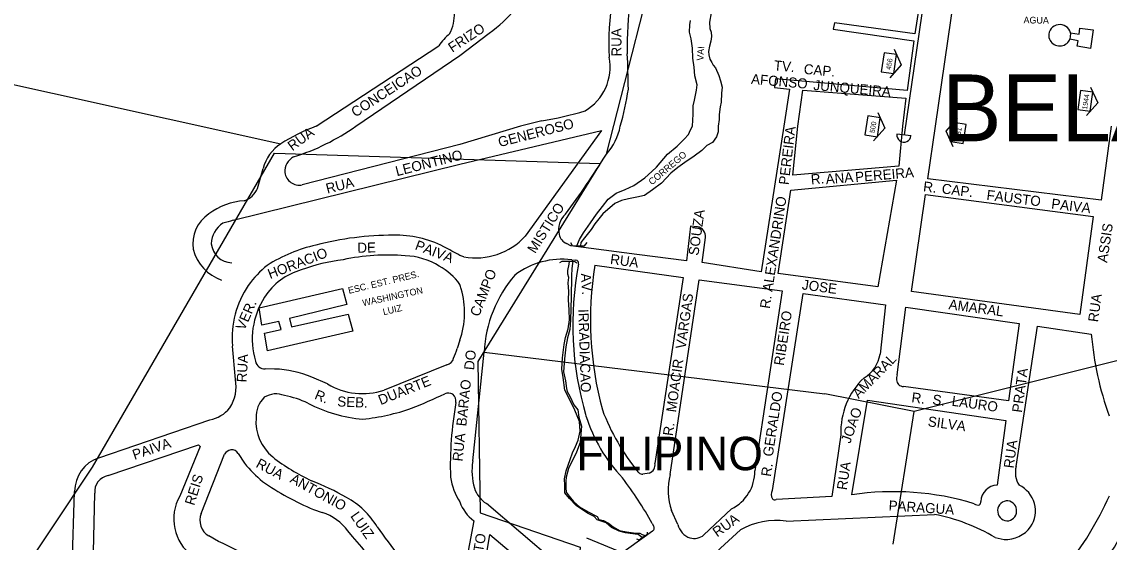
# Model space of a CAD drawing. Extents: x 325709 to 364434, y 7573432 to 7597073.
# Drawn here: x 337419 to 338070, y 7588753 to 7589064 of the extents above; entities that cross this region are included whole.
import ezdxf

# ---------------------------------------------------------------- set-up
doc = ezdxf.new("R2010")
doc.units = 0
for name, color, linetype in [('EDIFEXISTENT', 7, 'Continuous'), ('EDIFIDENTIF', 7, 'Continuous'), ('EDIFOBRAEXIS', 7, 'Continuous'), ('FORMATO', 7, 'Continuous'), ('LIMITE_BAIRROS_MUNICIPIOS', 7, 'Continuous'), ('LOGRADOURO', 7, 'Continuous'), ('LOGRADOURO_TEXTO', 7, 'Continuous'), ('NUM_REF', 7, 'Continuous'), ('TUBO_PEAD_GN_63', 7, 'Continuous')]:
    doc.layers.add(name, color=color, linetype=linetype)

# ---------------------------------------------------------------- blocks, each defined once
blk = doc.blocks.new('NUM_REF')
at = {"layer": 'NUM_REF'}
blk.add_lwpolyline([(-4.3125, 0.9375), (0, 3.75), (4.3125, 0.9375)], dxfattribs=at)
blk.add_lwpolyline([(2.875, -1.875), (2.875, 1.875), (-2.875, 1.875), (-2.875, -1.875)], close=True, dxfattribs=at)

msp = doc.modelspace()

# ---------------------------------------------------------------- linework, layer by layer
at = {"layer": 'EDIFEXISTENT'}
for p, q in [((338051.81, 7589056.99), (338052.19, 7589060.59)), ((338052.19, 7589060.59), (338060.07, 7589059.58)), ((338060.07, 7589059.58), (338058.51, 7589048.44)), ((338051.09, 7589053.04), (338046.15, 7589054.05)), ((338046.59, 7589057.82), (338051.81, 7589056.99)), ((338050.63, 7589049.78), (338051.09, 7589053.04)), ((338058.51, 7589048.44), (338050.63, 7589049.78)), ((337747.63, 7588932.35), (337748.55, 7588930.51)), ((337748.55, 7588930.51), (337751.34, 7588930.39)), ((337751.34, 7588930.39), (337753.58, 7588930.33)), ((337753.58, 7588930.33), (337756.01, 7588930.31)), ((337756.01, 7588930.31), (337757.52, 7588932.3)), ((337741.25, 7588920.34), (337742.68, 7588921.14)), ((337742.68, 7588921.14), (337746.99, 7588921.11)), ((337746.99, 7588921.11), (337748.95, 7588921.1)), ((337748.95, 7588921.1), (337750.16, 7588921.04)), ((337750.16, 7588921.04), (337751.4, 7588920.24)), ((337561.34, 7588893.15), (337611.22, 7588904.7)), ((337611.22, 7588904.7), (337613.85, 7588895.12)), ((337563.07, 7588882.93), (337561.34, 7588893.15)), ((337613.85, 7588895.12), (337579.56, 7588886.81)), ((337580.81, 7588881.87), (337614.63, 7588889.5)), ((337614.63, 7588889.5), (337617.41, 7588879.27)), ((337573.2, 7588885.02), (337563.07, 7588882.93)), ((337574.5, 7588880.18), (337573.2, 7588885.02)), ((337579.56, 7588886.81), (337580.81, 7588881.87)), ((337564.52, 7588877.96), (337574.5, 7588880.18)), ((337566.45, 7588867.51), (337564.52, 7588877.96)), ((337617.41, 7588879.27), (337566.45, 7588867.51)), ((337787.06, 7588754.88), (337788.73, 7588754.39)), ((337788.73, 7588754.39), (337790.52, 7588755.77)), ((337790.52, 7588755.77), (337792.3, 7588757.03)), ((337792.3, 7588757.03), (337793.57, 7588757.65)), ((337793.57, 7588757.65), (337793.53, 7588759.02))]:
    msp.add_line(p, q, dxfattribs=at)
for centre, radius, start, end in [((338040.18, 7589056.17), 6.62, 14.44536, 182.95924), ((338040.12, 7589056.57), 6.59, 186.41912, 10.98549)]:
    msp.add_arc(centre, radius, start, end, dxfattribs=at)
at = {"layer": 'EDIFOBRAEXIS'}
for points in [[(337820.46, 7589001.91), (337820.97, 7589009.19), (337821.01, 7589014.08), (337821.75, 7589017.47), (337823, 7589023.49), (337823.23, 7589026.79), (337822.03, 7589032.1), (337821.52, 7589037.33), (337820.73, 7589042.73), (337820.5, 7589048.67), (337819.76, 7589054.33), (337818.68, 7589058.17), (337818.99, 7589062.58), (337819.32, 7589065.31)], [(337831.73, 7589069.82), (337830.65, 7589064.3), (337830.82, 7589060.4), (337831.61, 7589058.28), (337831.92, 7589055.62), (337831.44, 7589052.94), (337830.65, 7589049.85), (337830.09, 7589046.66), (337830.4, 7589044.58), (337830.96, 7589042.16), (337832.04, 7589040.13), (337832.96, 7589038.52), (337834.22, 7589036.91), (337836.38, 7589032.28), (337837.22, 7589029.18), (337838.33, 7589025.29), (337837.84, 7589021.75), (337837.72, 7589016.3), (337837.06, 7589013.44), (337836.54, 7589008.95), (337836.51, 7589005.96), (337835.95, 7589001.91)], [(337751.34, 7588930.39), (337753.04, 7588934.14), (337755.35, 7588938.05), (337759.46, 7588944.11), (337763.2, 7588949.37), (337766.73, 7588953.78), (337770.13, 7588958.25), (337774.98, 7588961.84), (337780.19, 7588964.07), (337785.44, 7588966.49), (337791.94, 7588971.06), (337796.17, 7588974.74), (337799.03, 7588977.49), (337805.51, 7588985.21), (337811.35, 7588990.09), (337815.62, 7588994.27), (337818.17, 7588996.97), (337819.38, 7588999.67), (337820.46, 7589001.91)], [(337835.95, 7589001.91), (337835.97, 7588998.65), (337834.98, 7588995.63), (337832.58, 7588992.25), (337829.11, 7588990.37), (337826.1, 7588987.45), (337821.53, 7588983.95), (337816, 7588980.29), (337811.74, 7588977.2), (337807.56, 7588973.75), (337802.01, 7588967.85), (337796.71, 7588963.9), (337791.79, 7588960.46), (337787.19, 7588959.55), (337782.21, 7588958.55), (337778.09, 7588957.53), (337774, 7588955.66), (337766.82, 7588949.47), (337762.04, 7588943.54), (337759.86, 7588940.08), (337756.02, 7588935.21), (337753.82, 7588932.33), (337753.58, 7588930.33)], [(337790.52, 7588755.77), (337788.14, 7588757.62), (337786.27, 7588757.68), (337783.2, 7588758.16), (337780.54, 7588758.45), (337776.77, 7588759.6), (337772.01, 7588761.73), (337768.88, 7588764.47), (337763.52, 7588766.28), (337761.65, 7588768.28), (337757.73, 7588770.38), (337750.92, 7588774.84), (337746.96, 7588779.06), (337744.12, 7588782.4), (337744.15, 7588786.89), (337744.05, 7588790.85), (337744.99, 7588795.69), (337747.4, 7588802.4), (337748.8, 7588806.34), (337750.57, 7588810.26), (337752.1, 7588814.03), (337753.4, 7588819.43), (337752.93, 7588825.19), (337750.21, 7588831.93), (337747.19, 7588838.17), (337744.18, 7588843.87), (337743.09, 7588851.57), (337742.47, 7588856.55), (337742.72, 7588863.37), (337743.79, 7588871.25), (337744.6, 7588875.41), (337746.13, 7588880.65), (337746.91, 7588886.05), (337746.82, 7588892.06), (337746.33, 7588898.08), (337746.67, 7588903.02), (337746.17, 7588908.28), (337746.5, 7588911.45), (337746, 7588913.3), (337745.99, 7588915.66), (337746.83, 7588919.29), (337746.99, 7588921.11)], [(337748.95, 7588921.1), (337748.67, 7588918.38), (337748.41, 7588916.56), (337748.23, 7588912.55), (337748.17, 7588907.94), (337747.94, 7588903.7), (337747.91, 7588899.89), (337747.49, 7588885.87), (337747.17, 7588880.31), (337745.84, 7588875.25), (337744.79, 7588869.85), (337743.95, 7588862.65), (337743.42, 7588854.92), (337744.5, 7588849.56), (337745.18, 7588844.93), (337745.52, 7588843.23), (337747.23, 7588840.33), (337749.47, 7588835.06), (337751.89, 7588832.15), (337752.52, 7588827.71), (337754.08, 7588822.39), (337753.8, 7588817.73), (337753.38, 7588812.66), (337751.26, 7588806.83), (337746.42, 7588797.02), (337745.07, 7588791.83), (337744.77, 7588789.55), (337744.75, 7588785.57), (337744.93, 7588782.93), (337746.82, 7588780.48), (337749.46, 7588777.37), (337752.86, 7588774.15), (337758.07, 7588771.17), (337763.46, 7588768.39), (337764.48, 7588766.61), (337767.37, 7588765.85), (337770.25, 7588764.28), (337773.15, 7588762.11), (337776.87, 7588760), (337781.05, 7588759.11), (337786.63, 7588758.41), (337788.94, 7588758.3), (337790.35, 7588757.58), (337792.3, 7588757.03)]]:
    msp.add_lwpolyline(points, dxfattribs=at)
for centre, radius, start, end in [((338009.06, 7588771.68), 6.04, 88.51877, 264.4316), ((338008.35, 7588771.73), 6.05, 271.17829, 81.77207)]:
    msp.add_arc(centre, radius, start, end, dxfattribs=at)
at = {"layer": 'LIMITE_BAIRROS_MUNICIPIOS'}
for p, q in [((337695.94, 7588866.71), (337899.67, 7588841.8)), ((337953.19, 7588831.09), (337899.67, 7588841.8)), ((337940.59, 7588751.7), (337953.19, 7588831.09)), ((337757.11, 7588755.49), (337843.76, 7588720.08))]:
    msp.add_line(p, q, dxfattribs=at)
for points in [[(337769.02, 7588985.15), (337839.73, 7589261.51), (337695.54, 7589265.36), (337682.83, 7589413.05), (337659.48, 7589402.1), (337608.62, 7589481.66), (337302.83, 7589424.81), (337289.17, 7589608.02), (336886.18, 7589554.25), (337003.47, 7589398.07), (336925.28, 7589250.26), (337023.13, 7589198.92)], [(336888.36, 7588603.3), (337027.12, 7588760.98), (336904.2, 7588808.66), (336923.62, 7588900.77), (337052.69, 7588885.28), (337006.14, 7589000.16), (336918.76, 7589021.97), (337023.13, 7589198.92), (337208.32, 7589156.4), (337233.63, 7589066.99), (337574.29, 7588991.44)], [(336578.27, 7588232.62), (336880.81, 7588583.89), (337344.59, 7588516.4), (337388.39, 7588687.72), (337461.71, 7588797.86), (337570.55, 7588985.84), (337765.28, 7588979.55), (337692.2, 7588861.11), (337693.51, 7588770.52), (337753.37, 7588749.89), (337724.16, 7588368.65), (337953.39, 7588293.81), (337912.42, 7588074.06), (337856.05, 7588015.64)], [(338684.37, 7588906.03), (338334.39, 7588817.36), (338306.72, 7588889.49), (338200.72, 7588755.56), (338145.48, 7588849.37), (338078.28, 7588862.43), (337953.19, 7588831.09)]]:
    msp.add_lwpolyline(points, dxfattribs=at)
at = {"layer": 'LOGRADOURO'}
for p, q in [((337982.72, 7589252.71), (337953.58, 7589057.15)), ((337965.83, 7589001.91), (338001.82, 7589250.21)), ((337953.58, 7589057.15), (337905.36, 7589063.85)), ((337681.39, 7589044.28), (337698.88, 7589057.72)), ((337953, 7589053.06), (337948.93, 7589023.24)), ((337595.42, 7589001.91), (337668.79, 7589050.12)), ((337619.18, 7589001.91), (337681.39, 7589044.28)), ((337948.93, 7589023.24), (337870.08, 7589030.26)), ((337883.57, 7589001.91), (337886.47, 7589023.42)), ((337886.47, 7589023.42), (337948.02, 7589018.77)), ((337948.02, 7589018.77), (337946.13, 7589001.91)), ((337717.65, 7589001.91), (337681.39, 7588990.95)), ((337730.41, 7589005.17), (337717.74, 7589001.91)), ((337875.17, 7589001.91), (337861.67, 7588914.72)), ((337880.45, 7588972.6), (337883.57, 7589001.91)), ((337946.13, 7589001.91), (337943.97, 7588977.99)), ((337961.22, 7588970.49), (337965.83, 7589001.91)), ((338070.89, 7589001.91), (338065.03, 7588957.74)), ((337681.39, 7588979.29), (337766.19, 7588999.33)), ((337766.19, 7588999.33), (337720.44, 7588936.2)), ((337681.39, 7588990.95), (337587.12, 7588966.76)), ((337545.87, 7588945.6), (337681.39, 7588979.29)), ((337560.31, 7588964.75), (337563.74, 7588976.6)), ((337943.97, 7588977.99), (337880.45, 7588972.6)), ((337879.28, 7588963.6), (337942.47, 7588969.69)), ((337942.47, 7588969.69), (337931.39, 7588905.7)), ((338065.03, 7588957.74), (337961.22, 7588970.49)), ((337871.74, 7588913.75), (337879.28, 7588963.6)), ((337951.48, 7588902.95), (337959.84, 7588961.11)), ((337959.84, 7588961.11), (338060.21, 7588947.96)), ((338060.21, 7588947.96), (338052.13, 7588889.29)), ((337683.88, 7588923.79), (337681.39, 7588924.64)), ((337748.28, 7588921.95), (337750.67, 7588921.72)), ((337762.05, 7588918.69), (337815.04, 7588911.41)), ((337815.04, 7588911.41), (337798.1, 7588800.13)), ((337807.13, 7588793.4), (337824.58, 7588909.95)), ((337824.58, 7588909.95), (337874.24, 7588903.3)), ((337931.39, 7588905.7), (337871.74, 7588913.75)), ((338052.13, 7588889.29), (337951.48, 7588902.95)), ((337868.28, 7588783.85), (337886.64, 7588901.77)), ((337886.64, 7588901.77), (337935.98, 7588894.97)), ((337935.98, 7588894.97), (337932.71, 7588865.47)), ((337942.9, 7588853.11), (337948.08, 7588893.56)), ((337948.08, 7588893.56), (338015.85, 7588883.93)), ((338015.85, 7588883.93), (338009.51, 7588837.62)), ((338014.02, 7588798.19), (338026.83, 7588882.2)), ((338026.83, 7588882.2), (338059.05, 7588877.54)), ((337547.19, 7588850.28), (337545.43, 7588870.37)), ((337681.39, 7588873.77), (337679.77, 7588868.87)), ((337689.07, 7588801.57), (337695.94, 7588866.71)), ((337673.71, 7588859.06), (337636.04, 7588843.98)), ((337570.59, 7588856.57), (337565.05, 7588856.64)), ((337602.29, 7588847.68), (337592.86, 7588851.63)), ((338009.51, 7588837.62), (337946.8, 7588846.15)), ((337915.74, 7588781.23), (337925.24, 7588838)), ((337925.24, 7588838), (338007.95, 7588825.72)), ((337652.57, 7588833.14), (337652.57, 7588833.14)), ((337465.44, 7588803.46), (337531.92, 7588826.09)), ((338007.95, 7588825.72), (338002.73, 7588787.12)), ((337909.24, 7588817.18), (337903.87, 7588780.35)), ((337526.09, 7588810.19), (337513.99, 7588780.57)), ((337526.77, 7588770.2), (337540.69, 7588805.7)), ((337548.73, 7588805.96), (337552.66, 7588800.17)), ((337794.6, 7588794.3), (337790.76, 7588793.72)), ((337449.41, 7588735.26), (337451.03, 7588783.31)), ((337461.85, 7588726.06), (337463.02, 7588782.25)), ((337903.87, 7588780.35), (337870.66, 7588778.42)), ((337593.93, 7588772.54), (337599.12, 7588770.65)), ((337738.45, 7588740.96), (337697.25, 7588776.12)), ((337843.84, 7588772.91), (337827.33, 7588757.28)), ((337689.71, 7588765.73), (337681.39, 7588720.91)), ((337811.8, 7588763.49), (337807.95, 7588771.82)), ((337876.59, 7588765.61), (337965.34, 7588769.56)), ((337796.68, 7588759.6), (337761.25, 7588734.2)), ((337796.45, 7588764.19), (337797.21, 7588762.64)), ((337825.08, 7588738.25), (337849.21, 7588760.3)), ((337537.14, 7588753.35), (337531.26, 7588756.66)), ((337681.39, 7588649.88), (337699.37, 7588757.6)), ((337699.37, 7588757.6), (337735.5, 7588726.99)), ((338001.5, 7588755.77), (338006.89, 7588754.6))]:
    msp.add_line(p, q, dxfattribs=at)
for points in [[(337905.36, 7589063.85), (337904.71, 7589060.05), (337953, 7589053.06)], [(337870.08, 7589030.26), (337869.6, 7589025.09), (337878.58, 7589024.19), (337875.17, 7589001.91)], [(337756.26, 7589011.15), (337756.26, 7589011.15), (337756.26, 7589011.15)], [(337823.48, 7588941.79), (337819.42, 7588942.05), (337816.85, 7588921.45), (337787.29, 7588925.23), (337747.87, 7588930.32), (337745.11, 7588931.72)], [(337861.67, 7588914.72), (337826.41, 7588920.3), (337828.35, 7588935.36)], [(337874.24, 7588903.3), (337874.24, 7588903.3), (337857.76, 7588795.63)], [(337471.09, 7588792.84), (337525.1, 7588811.13), (337526.09, 7588810.19)]]:
    msp.add_lwpolyline(points, dxfattribs=at)
for centre, radius, start, end in [((337938.22, 7589051.53), 167.77, 158.77259, 182.84387), ((337943.89, 7589051.25), 162.45, 158.8305, 182.07832), ((337658.5, 7589117.02), 71.74, 304.25603, 338.70866), ((337652.95, 7589069.17), 25.28, 331.85593, 1.39882), ((337701.57, 7589026.89), 40.18, 130.94196, 144.67646), ((337021.23, 7589011.47), 761.08, 0.95328, 2.55181), ((337741.16, 7589037.18), 30.09, 300.10612, 11.54747), ((337611.36, 7589049.61), 172.73, 343.97021, 351.5184), ((337700.18, 7589194.82), 192.04, 279.05704, 286.97934), ((337637.6, 7588890.27), 119.35, 110.69977, 122.0367), ((337541.24, 7589112.95), 135.66, 287.47839, 305.06738), ((337742.85, 7589008.65), 35.17, 318.08114, 348.9565), ((337588.41, 7588970.22), 25.48, 123.63763, 165.51212), ((337586.24, 7588975.02), 9.53, 116.50114, 185.22671), ((337273.28, 7589295.4), 584.82, 323.71184, 327.96099), ((337585.48, 7588975.43), 8.82, 188.33095, 280.76537), ((337548.56, 7588969.41), 12.65, 287.66636, 338.36737), ((337555.32, 7588917.52), 39.95, 94.19082, 126.93239), ((337543.02, 7588931.58), 21.37, 123.23187, 188.96306), ((337752.55, 7588940.15), 12.06, 130.82822, 194.54047), ((337547.83, 7588931.23), 15.06, 122.65851, 178.68817), ((337782.58, 7588069.36), 907.65, 105.11721, 105.52126), ((337822.44, 7588935.94), 5.94, 354.33521, 79.92728), ((337641.6, 7588753.13), 183.57, 89.98006, 104.5962), ((337643.18, 7588874.54), 62.19, 62.66391, 91.39412), ((337691.2, 7588962.28), 39.18, 259.22603, 318.26115), ((337748, 7588938.33), 7.22, 189.63154, 246.43791), ((337547.46, 7588934.75), 26.36, 194.2774, 251.09089), ((337545.01, 7588932.53), 12.28, 184.48233, 269.92489), ((337614.83, 7588843.19), 89.73, 102.54233, 122.78417), ((337426.52, 7588457.19), 532.42, 61.39911, 62.57648), ((337626.7, 7588804.37), 118.6, 97.35318, 109.77622), ((337638.53, 7588792.58), 132.21, 85.57465, 101.78738), ((337647.3, 7588883.13), 41.29, 58.10089, 88.00847), ((337742.48, 7588876.06), 46.26, 82.79996, 127.48488), ((337750.73, 7588920.06), 1.67, 35.89566, 92.12721), ((337604.92, 7588870.55), 61.71, 128.82013, 144.18654), ((337597.81, 7588877.99), 39.62, 106.47767, 146.92716), ((337651.83, 7588886.47), 36.12, 35.08484, 61.41265), ((337940.66, 7588883.11), 191.73, 169.07728, 196.49469), ((337750.38, 7588919.85), 2.06, 348.41338, 34.83209), ((337969.93, 7588886.25), 210.39, 171.12963, 194.90387), ((337771.8, 7588863.11), 75.94, 139.16988, 177.28475), ((337601.47, 7588875.15), 56.25, 145.92833, 184.87191), ((337633.03, 7588890.5), 51.18, 15.94993, 19.08011), ((337633.03, 7588890.5), 51.17, 340.91842, 15.95139), ((337603.43, 7588874.56), 46.2, 147.17484, 196.66125), ((338250.72, 7588893.73), 192.36, 184.82756, 199.83046), ((337614.31, 7588888.87), 68.45, 337.80071, 343.01248), ((337912.86, 7588868.63), 20.1, 300.66614, 350.93628), ((337564.82, 7588862.38), 5.74, 190.66462, 272.32788), ((337672.18, 7588864.58), 5.73, 285.53527, 344.05906), ((337525.06, 7588845.91), 22.56, 326.19091, 11.17812), ((337569.14, 7588797.43), 59.16, 66.35712, 88.598), ((337954.14, 7588818.85), 44.93, 133.67487, 182.1221), ((337949.02, 7588850.99), 6.48, 160.89704, 215.29), ((337623.15, 7588882.18), 40.31, 238.84476, 288.64735), ((337946.75, 7588850.85), 4.69, 230.08401, 270.71526), ((337576.05, 7588827.9), 16.54, 134.54191, 182.25273), ((337571.51, 7588828.24), 13.45, 68.19212, 121.63734), ((337565.96, 7588785.28), 56.44, 64.16648, 79.22572), ((337525.85, 7589149.94), 341.21, 291.80146, 295.42752), ((337674.48, 7588836.61), 5.6, 59.92996, 112.32252), ((337673, 7588837.17), 6.06, 353.75627, 44.95002), ((337527.9, 7588846.01), 20.32, 281.40934, 321.47918), ((337630.28, 7588912.2), 85.86, 242.4388, 265.39344), ((337610.84, 7588951.42), 125.43, 275.73998, 289.43516), ((337890.94, 7588798.89), 215.24, 169.93216, 181.89321), ((337893.08, 7588880.09), 135.25, 200.76689, 218.95333), ((337586.61, 7588825.08), 27.17, 175.40952, 230.95743), ((337847.37, 7588856.73), 94.8, 197.2191, 223.5501), ((337545.34, 7588802.66), 5.55, 99.68795, 146.83977), ((337545.33, 7588804.59), 3.66, 21.8997, 104.67868), ((337472.3, 7588783.33), 21.27, 108.82645, 180.04747), ((337609.56, 7588845.65), 72.85, 218.63347, 230.66732), ((337644.57, 7588899.83), 121.76, 231.9333, 244.77112), ((337727.01, 7588795.75), 38.38, 171.26961, 195.93156), ((337793.07, 7588799.18), 5.12, 287.32555, 10.67378), ((338027.96, 7588794.8), 14.35, 166.31447, 212.53702), ((337472.79, 7588783.17), 9.82, 99.98826, 185.35017), ((337714.44, 7588797.96), 39.11, 189.09118, 212.32625), ((337791.3, 7588798.01), 4.49, 220.89349, 247.79637), ((337790.3, 7588794.86), 1.23, 235.37674, 292.14321), ((337842.95, 7588783.96), 37.05, 165.23177, 199.13646), ((337833, 7588795.18), 24.77, 295.97634, 1.04999), ((337655.3, 7588920.51), 160.19, 234.98738, 247.47455), ((337532.65, 7588636.35), 164.67, 60.54143, 68.62441), ((337706.46, 7588790.72), 17.26, 198.6252, 237.75732), ((337585.72, 7588645.94), 241.65, 29.29874, 37.01677), ((338003.22, 7588776.79), 10.33, 92.73855, 176.89142), ((338008.41, 7588771.58), 17.2, 326.59968, 64.29912), ((337537.82, 7588766.8), 27.53, 149.97562, 233.61258), ((337589.31, 7588735.99), 50.04, 31.50115, 60.9185), ((337872.75, 7588781.42), 5.09, 151.5023, 209.01827), ((337869.89, 7588780.5), 2.21, 224.12777, 290.35036), ((337940.9, 7588620.19), 163, 72.84628, 98.8783), ((337891.09, 7588860.57), 195.8, 320.97849, 335.93511), ((337704.62, 7588785.41), 24.69, 199.80464, 232.84423), ((337991.53, 7588779.84), 4.67, 236.7747, 278.47396), ((337989.92, 7588777.14), 2.99, 320.191, 4.09806), ((337536.67, 7588765.96), 10.77, 156.80805, 239.81259), ((337590.16, 7588742.01), 30, 36.02848, 72.61923), ((337870.88, 7588721.8), 44.17, 82.57887, 119.37495), ((337943.19, 7588657.18), 114.54, 59.39728, 78.84689), ((337285.39, 7588470.92), 437.76, 32.30909, 41.26855), ((338002.84, 7589023.54), 453.72, 215.17844, 217.9642), ((337795.9, 7588761.2), 1.78, 295.83962, 358.72368), ((337795.85, 7588761.39), 1.85, 352.71417, 42.39217), ((337822.93, 7588766.22), 11.46, 193.76393, 249.90706), ((338007.74, 7588773.34), 18.76, 267.38596, 323.23929), ((337455.45, 7588570.16), 200.58, 58.93644, 65.96485), ((337821.32, 7588764.84), 9.67, 256.08494, 308.50717), ((337874.59, 7588867.14), 230.25, 322.11245, 331.87449)]:
    msp.add_arc(centre, radius, start, end, dxfattribs=at)
at = {"layer": 'TUBO_PEAD_GN_63'}
for p, q in [((337984.55, 7589255.06), (337947.04, 7588996.84)), ((337951.21, 7588996.21), (337942.75, 7588997.08))]:
    msp.add_line(p, q, dxfattribs=at)
msp.add_arc((337946.98, 7588996.65), 4.25, 174.1421, 354.1421, dxfattribs=at)

# ---------------------------------------------------------------- block references
at = {"layer": 'FORMATO'}
for p, xscale, yscale, rotation in [((337937.96, 7589039.72), 1.9999999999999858, 1.9999999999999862, -98.26508109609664), ((338055.46, 7589017.09), 1.9999999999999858, 1.9999999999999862, -98.26508109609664), ((337928.24, 7589001.91), 1.9999999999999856, 1.9999999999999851, -98.63271355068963), ((337979.58, 7588997.88), 1.9999999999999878, 1.9999999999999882, 81.33720200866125)]:
    msp.add_blockref('NUM_REF', p, dxfattribs=dict(at, xscale=xscale, yscale=yscale, rotation=rotation))

# ---------------------------------------------------------------- texts
for s, rotation, p in [('456', 80.77731, (337939.12, 7589035.48)), ('1944', 80.77731, (338056.44, 7589011.71)), ('500', 80.40968, (337929.39, 7588997.67)), ('481', 81.05538, (337980.51, 7588994.19))]:
    msp.add_text(s, height=3, rotation=rotation).set_placement(p)
at = {"layer": 'EDIFIDENTIF'}
for s, rotation, p in [('AGUA', 359.32978, (338018.49, 7589063.5)), ('VAI', 86.11322, (337827.03, 7589041.04)), ('CORREGO', 40.25202, (337796.31, 7588966.46)), ('ESC. EST. PRES.', 13.59762, (337615.11, 7588901.55)), ('WASHINGTON', 12.24276, (337623.59, 7588894.15)), ('LUIZ', 13.41347, (337635.85, 7588888.74))]:
    msp.add_text(s, height=4, rotation=rotation, dxfattribs=at).set_placement(p)
at = {"layer": 'LIMITE_BAIRROS_MUNICIPIOS'}
for s, height, p in [('BELA VISTA', 40, (337969.69, 7588992.9)), ('FILIPINO', 20, (337751.15, 7588796.01))]:
    msp.add_text(s, height=height, dxfattribs=at).set_placement(p)
at = {"layer": 'LOGRADOURO_TEXTO'}
for s, rotation, p in [('FRIZO', 33.30949, (337676.92, 7589045.82)), ('RUA', 90.21413, (337778.08, 7589043.67)), ('TV.', 354.90903, (337868.97, 7589035.44)), ('CAP.', 354.90903, (337886.88, 7589033.27)), ('CONCEICAO', 33.30949, (337618.93, 7589007.09)), ('AFONSO', 354.90903, (337855.38, 7589027.33)), ('JUNQUEIRA', 354.90903, (337892.69, 7589023.67)), ('RUA', 36.45128, (337581.23, 7588986.88)), ('GENEROSO', 14.39361, (337705.16, 7588989.38)), ('PEREIRA', 83.13607, (337878.02, 7588966.57)), ('LEONTINO', 14.39361, (337643.75, 7588971.96)), ('ANA', 4.84823, (337900.43, 7588967.22)), ('PEREIRA', 4.84823, (337918.06, 7588968.47)), ('RUA', 14.39361, (337602.16, 7588961.55)), ('R.', 4.84823, (337891.55, 7588967.08)), ('R.', 352.99869, (337958.24, 7588963)), ('CAP.', 352.99869, (337969.36, 7588961.73)), ('FAUSTO', 352.99869, (337996.14, 7588957.89)), ('MISTICO', 57.76295, (337726.42, 7588925.33)), ('R. ALEXANDRINO', 81.43879, (337866.73, 7588892.45)), ('PAIVA', 352.99869, (338034.86, 7588952.72)), ('SOUZA', 82.07773, (337824.04, 7588924.26)), ('ASSIS', 81.40338, (338068.47, 7588919.98)), ('HORACIO', 21.12765, (337567.93, 7588910.39)), ('DE', 1.1709, (337620.15, 7588926.18)), ('PAIVA', 339.10731, (337654.11, 7588928.31)), ('RUA', 352.36519, (337771.03, 7588919.5)), ('CAMPO', 68.70232, (337692.83, 7588887.51)), ('AV.', 273.57254, (337753.76, 7588913.76)), ('JOSE', 352.31134, (337885.74, 7588904.29)), ('VER.', 66.37298, (337552.54, 7588879.28)), ('VARGAS', 82.07773, (337816.39, 7588868.33)), ('AMARAL', 352.27043, (337973.48, 7588892.46)), ('RUA', 82.09859, (338063.02, 7588884.41)), ('IRRADIACAO', 271.75889, (337752.28, 7588892.4)), ('RIBEIRO', 81.2974, (337875.1, 7588858.36)), ('RUA', 87.06946, (337553.9, 7588848.48)), ('DO', 83.98345, (337689.86, 7588855.74)), ('AMARAL', 45.7066, (337919.92, 7588838.54)), ('MOACIR', 82.07773, (337810.66, 7588830.42)), ('PRATA', 82.19825, (338017.53, 7588830.23)), ('DUARTE', 21.81567, (337634.05, 7588834.93)), ('R.', 337.29415, (337594.03, 7588838.91)), ('BARAO', 83.98345, (337685.2, 7588822.09)), ('SEB.', 357.45984, (337607.98, 7588834.24)), ('GERALDO', 81.2974, (337868.49, 7588803.9)), ('R.', 352.24584, (337951.24, 7588836.75)), ('S.', 352.24584, (337963.75, 7588835.49)), ('LAURO', 352.24584, (337975.33, 7588834.64)), ('JOAO', 70.6611, (337914.85, 7588811.65)), ('SILVA', 352.24584, (337961, 7588822.39)), ('RUA', 83.98345, (337682.93, 7588801.08)), ('R.', 82.07773, (337808.74, 7588816.29)), ('PAIVA', 18.79972, (337486.78, 7588802.2)), ('RUA', 82.29235, (338012.55, 7588796.91)), ('RUA', 331.81345, (337558.95, 7588798.15)), ('R.', 81.2974, (337867.4, 7588791.9)), ('RUA', 81.69526, (337912.76, 7588783.9)), ('REIS', 72.6048, (337522.48, 7588774.56)), ('ANTONIO', 331.10866, (337579.31, 7588789.09)), ('PARAGUA', 356.22314, (337937.68, 7588771.98)), ('LUIZ', 304.86946, (337615.67, 7588768.56)), ('RUA', 35.63288, (337835.29, 7588755.72)), ('NETO', 80.52565, (337693.47, 7588735.7))]:
    msp.add_text(s, height=6, rotation=rotation, dxfattribs=at).set_placement(p)

doc.saveas('drawing.dxf')
